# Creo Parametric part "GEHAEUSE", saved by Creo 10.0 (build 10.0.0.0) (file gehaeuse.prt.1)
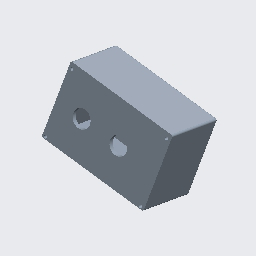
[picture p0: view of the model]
Units: millimeter Newton Second (mmNs); MM, TONNE, SECS

Created from: PRT0002.PRT

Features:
  1. datum plane "RIGHT"
  2. datum plane "TOP"
  3. datum plane "FRONT"
  4. coordinate system
  5. extrusion "Profil 1"
  6. extruded cut "Profil 2"
  7. extruded cut "Profil 3"
  8. extrusion "Profil 4"
  9. extruded cut "Profil 5"
  10. datum axis "A_7"
  11. datum axis "A_8"
  12. hole "Bohrung 1"
  13. datum axis "A_10"
  14. datum axis "A_11"
  15. datum axis "A_12"
  16. hole "Bohrung 2"
  17. datum axis "A_14"
  18. hole "Bohrung 3"
  19. datum axis "A_16"
  20. hole "Bohrung 4"
  21. round "Rundung 2"
  22. mirror "Spiegeln 1"
  23. extruded cut "Profil 3 (2)"

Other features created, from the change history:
  extruded cut "Profil 3"
  round "Rundung 1" (4 times)
  extruded cut "Profil 4"
  datum axis "A_7"
  datum axis "A_8"
  datum axis "A_9"

Surfaces: 16 cylinder, 13 plane, 4 torus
